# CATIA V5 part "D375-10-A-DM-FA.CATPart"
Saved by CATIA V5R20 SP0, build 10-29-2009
Part number: D375-10-A-DM-FA
Bounding box of the stored display mesh (mm): x -12 to 0, y -5 to 5, z -5 to 5
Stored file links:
  C:\Users\Utente\Desktop\IO LAVORO\3D X SITO CF\X SITO\PLASTICA\D375\D375-10-A-DM-FA.CATPart
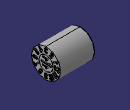
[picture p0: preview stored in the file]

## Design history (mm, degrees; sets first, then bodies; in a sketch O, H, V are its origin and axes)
Set1
  DatumSurface1 to DatumSurface216 "D375-10-A-DM-FA"
Body1 (main body)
